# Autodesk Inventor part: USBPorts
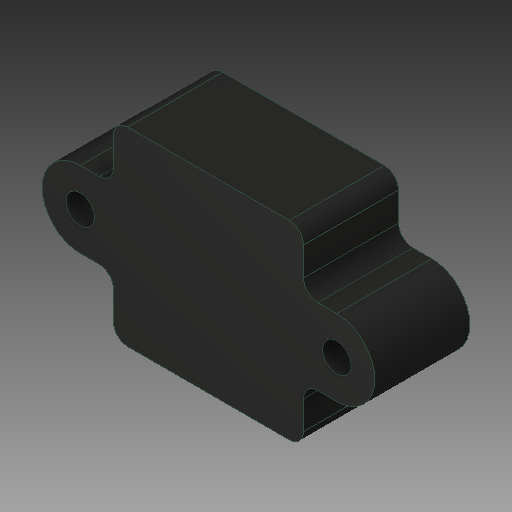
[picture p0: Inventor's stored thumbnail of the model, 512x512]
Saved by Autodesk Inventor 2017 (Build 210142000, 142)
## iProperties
Created: 2017-05
Part Number: USBPorts
Material: Generic
Document SubType Name: Modeling
Designer: Savy
Density: 1 g/cm^3
Appearance: Default
Author: Savy
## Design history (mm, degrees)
feature "SOLID1"
body "Solid1"
